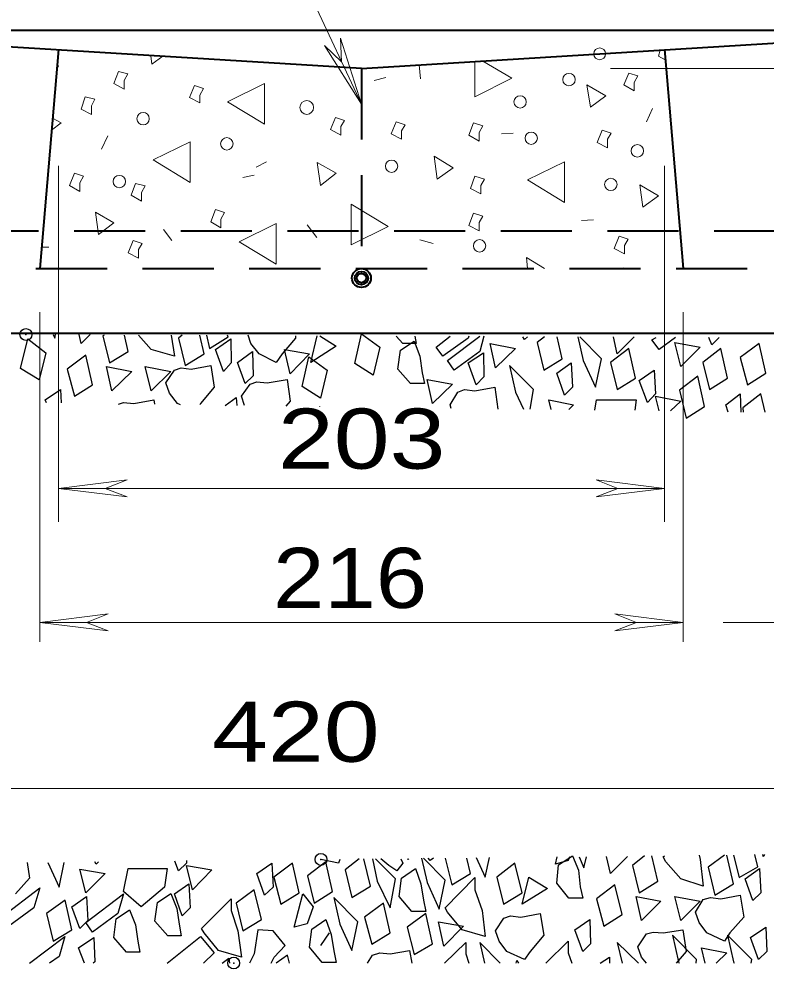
# Model space of a CAD drawing. Extents: x 312583 to 312854, y 144419 to 144597.
# Drawn here: x 312650.91 to 312660.36, y 144443.05 to 144455.06 of the extents above; entities that cross this region are included whole.
import ezdxf

# ---------------------------------------------------------------- set-up
doc = ezdxf.new("R2010")
doc.units = 0
doc.header["$LTSCALE"] = 0.3
doc.header["$PDMODE"] = 32
doc.header["$PDSIZE"] = 0.15
doc.linetypes.add('MEDIUM_DASHED', pattern=[4.5, 3, -1.5])
doc.layers.add('1', color=7, linetype='Continuous', lineweight=25)
doc.layers.add('2', color=7, linetype='Continuous', lineweight=13)

msp = doc.modelspace()

# ---------------------------------------------------------------- linework, layer by layer
at = {"layer": '1', "lineweight": 40}
for p, q in [((312655.2448, 144454.4368), (312647.3405, 144454.9198)), ((312647.5781, 144454.9198), (312662.9115, 144454.9198)), ((312655.2448, 144454.4368), (312663.1491, 144454.9198)), ((312651.4115, 144454.6744), (312651.1738, 144451.9068)), ((312659.0781, 144454.6744), (312659.3158, 144451.9068)), ((312626.2571, 144451.0864), (312669.6198, 144451.0864))]:
    msp.add_line(p, q, dxfattribs=at)
at = {"layer": '1', "linetype": 'MEDIUM_DASHED', "lineweight": 40}
for p, q in [((312655.2448, 144454.4368), (312655.2448, 144451.9068)), ((312643.5071, 144452.3821), (312667.7031, 144452.3821)), ((312628.1738, 144451.9068), (312667.4655, 144451.9068))]:
    msp.add_line(p, q, dxfattribs=at)
at = {"layer": '1'}
for p, q in [((312652.2931, 144450.8564), (312652.2471, 144451.0634)), ((312653.2515, 144450.8258), (312653.1978, 144451.0634)), ((312653.5581, 144451.0404), (312653.5505, 144451.0634)), ((312654.7158, 144451.0558), (312654.9228, 144450.9254)), ((312656.6018, 144451.0481), (312656.5941, 144451.0251)), ((312656.7935, 144451.0481), (312656.7398, 144450.8564)), ((312657.7825, 144450.7644), (312657.7211, 144451.0404)), ((312658.2808, 144450.7644), (312658.0048, 144451.0404)), ((312651.4345, 144450.3734), (312651.4421, 144450.2048)), ((312657.3761, 144450.1281), (312657.4221, 144450.3734)), ((312653.5198, 144450.1741), (312653.6578, 144450.2738)), ((312653.6578, 144450.2738), (312653.6655, 144450.1741)), ((312659.2851, 144450.2278), (312659.1548, 144450.1051)), ((312660.0365, 144450.3198), (312660.0441, 144450.0898)), ((312653.2055, 144450.1971), (312653.1978, 144450.1818)), ((312654.7158, 144450.1588), (312654.7158, 144450.1664)), ((312657.9281, 144450.1818), (312657.8668, 144450.1204)), ((312658.9938, 144444.1558), (312658.9171, 144444.4778)), ((312659.9521, 144444.1251), (312659.8678, 144444.4854)), ((312660.2588, 144444.3398), (312660.2205, 144444.4931)), ((312655.3598, 144444.0944), (312655.2755, 144444.4394)), ((312655.6741, 144444.1864), (312655.4211, 144444.4394)), ((312656.3028, 144444.1711), (312656.0268, 144444.4471)), ((312656.6248, 144444.2554), (312656.5788, 144444.4471)), ((312654.7311, 144443.3431), (312654.8385, 144443.5041)), ((312651.4191, 144443.2051), (312651.2965, 144443.1208)), ((312653.4815, 144443.1208), (312653.5658, 144443.1821)), ((312653.5658, 144443.1821), (312653.5735, 144443.1208)), ((312656.5635, 144443.2358), (312656.6018, 144443.1208)), ((312657.8591, 144443.2511), (312657.9051, 144443.1208)), ((312658.2655, 144443.1208), (312658.3805, 144443.1974)), ((312658.3805, 144443.1974), (312658.3805, 144443.1208)), ((312659.4768, 144443.1208), (312659.4845, 144443.1668)), ((312659.8678, 144443.2511), (312659.7298, 144443.1208)), ((312660.1745, 144443.1208), (312660.1821, 144443.1668))]:
    msp.add_line(p, q, dxfattribs=at)
for points in [[(312651.3425, 144451.0711), (312651.3655, 144451.0251), (312651.3731, 144451.0711)], [(312651.8101, 144451.0711), (312651.6951, 144450.9561), (312651.6721, 144451.0711)], [(312651.9865, 144451.0634), (312651.9711, 144451.0558), (312652.0555, 144450.7108), (312652.2931, 144450.8564)], [(312652.8375, 144451.0634), (312652.8758, 144450.7951), (312652.5845, 144450.8794), (312652.4235, 144451.0634)], [(312652.9755, 144451.0634), (312652.9295, 144451.0251), (312653.0138, 144450.6801), (312653.2515, 144450.8258)], [(312653.2821, 144451.0634), (312653.3205, 144450.8948), (312653.5581, 144451.0404)], [(312654.2405, 144450.8258), (312654.1638, 144450.7184), (312653.9491, 144450.8258), (312653.8418, 144450.9561), (312653.8111, 144451.0634)], [(312654.4091, 144451.0558), (312654.4091, 144451.0251), (312654.2405, 144450.8258)], [(312654.9228, 144450.9254), (312654.6008, 144450.7184), (312654.6851, 144451.0558)], [(312655.9195, 144451.0481), (312655.9348, 144450.9561), (312655.7661, 144450.9561), (312655.6818, 144451.0481)], [(312656.5941, 144451.0251), (312656.2721, 144450.7951), (312656.1878, 144450.9101), (312656.3641, 144451.0481)], [(312656.7398, 144450.8564), (312656.4178, 144450.6188), (312656.3335, 144450.7414), (312656.7398, 144451.0481)], [(312657.3455, 144451.0404), (312657.3071, 144451.0098), (312657.2841, 144451.0404)], [(312657.5601, 144451.0404), (312657.4681, 144450.9714), (312657.5525, 144450.6188), (312657.7825, 144450.7644)], [(312657.9818, 144451.0404), (312658.0508, 144450.7414), (312658.2041, 144450.4041), (312658.2808, 144450.7644)], [(312658.6948, 144451.0404), (312658.4801, 144450.8258), (312658.4341, 144451.0404)], [(312659.2161, 144451.0328), (312659.0091, 144450.8794), (312658.9171, 144451.0021), (312658.9708, 144451.0328)], [(312659.7681, 144451.0328), (312659.6761, 144450.9408), (312659.6378, 144451.0328)], [(312652.9525, 144450.1818), (312652.9141, 144450.1971), (312652.8145, 144450.3274), (312652.7685, 144450.4578), (312652.8758, 144450.6188), (312652.9601, 144450.6494), (312653.0905, 144450.6341), (312653.3358, 144450.6801), (312653.3818, 144450.4041), (312653.2055, 144450.1971)], [(312657.4221, 144450.3734), (312657.1155, 144450.6801), (312657.1921, 144450.3428), (312657.2918, 144450.1281)], [(312653.7651, 144450.1741), (312653.7268, 144450.2891), (312653.8341, 144450.4424), (312653.9185, 144450.4731), (312654.0488, 144450.4578), (312654.3018, 144450.5038), (312654.3401, 144450.2278), (312654.2865, 144450.1664)], [(312651.2581, 144450.2048), (312651.2428, 144450.2431), (312651.4345, 144450.3734)], [(312656.3795, 144450.1358), (312656.3641, 144450.1818), (312656.4638, 144450.3428), (312656.5481, 144450.3734), (312656.6785, 144450.3581), (312656.9315, 144450.4041), (312656.9698, 144450.1281)], [(312652.1705, 144450.1894), (312652.2318, 144450.2124), (312652.3621, 144450.1971), (312652.6151, 144450.2431), (312652.6228, 144450.1894)], [(312657.6445, 144450.1204), (312657.6138, 144450.2431), (312657.9281, 144450.1818)], [(312658.1965, 144450.1128), (312658.2195, 144450.2431), (312658.7178, 144450.2431), (312658.7025, 144450.1128)], [(312659.0091, 144450.1051), (312658.9631, 144450.2891), (312659.2851, 144450.2278)], [(312659.8831, 144450.0898), (312659.8525, 144450.1818), (312660.0365, 144450.3198)], [(312660.3508, 144450.0898), (312660.2971, 144450.3198), (312660.0671, 144450.1434), (312660.0748, 144450.0898)], [(312657.8745, 144444.4624), (312657.8591, 144444.4164), (312657.6981, 144444.3704), (312657.7211, 144444.4624)], [(312657.9971, 144444.4624), (312658.0585, 144444.3244), (312658.0891, 144444.4624)], [(312658.6105, 144444.4701), (312658.3958, 144444.2554), (312658.3421, 144444.4701)], [(312658.8251, 144444.4778), (312658.6718, 144444.3551), (312658.7561, 144444.0101), (312658.9938, 144444.1558)], [(312659.5151, 144444.4854), (312659.5305, 144444.4318), (312659.5688, 144444.0944), (312659.2851, 144444.1864), (312659.0935, 144444.4011), (312659.0628, 144444.4624), (312659.0781, 144444.4778)], [(312659.8371, 144444.4854), (312659.6301, 144444.3321), (312659.7145, 144443.9794), (312659.9521, 144444.1251)], [(312659.9521, 144444.4854), (312660.0211, 144444.2018), (312660.2588, 144444.3398)], [(312660.3431, 144444.4931), (312660.3278, 144444.4701), (312660.3201, 144444.4931)], [(312651.0128, 144444.3934), (312651.0435, 144444.1941), (312650.8671, 144443.9948)], [(312651.2735, 144444.3934), (312651.4191, 144444.0791), (312651.4805, 144444.3934)], [(312651.9175, 144444.4011), (312651.8868, 144444.3704), (312651.8715, 144444.4011)], [(312653.0291, 144444.4164), (312653.0291, 144444.3858), (312652.9295, 144444.2861), (312652.8835, 144444.4088)], [(312654.9688, 144444.4318), (312654.9535, 144444.3858), (312654.7311, 144444.4318)], [(312655.2141, 144444.4394), (312655.0378, 144444.3014), (312655.1221, 144443.9488), (312655.3598, 144444.0944)], [(312655.3828, 144444.4394), (312655.4441, 144444.1558), (312655.6051, 144443.8184), (312655.6741, 144444.1864)], [(312655.7431, 144444.4394), (312655.7661, 144444.3858), (312655.6895, 144444.2861), (312655.5898, 144444.3551), (312655.4901, 144444.4394)], [(312655.8275, 144444.4394), (312655.8351, 144444.4318), (312655.8428, 144444.4394)], [(312656.0038, 144444.4471), (312656.0728, 144444.1404), (312656.2261, 144443.8031), (312656.3028, 144444.1711)], [(312656.1571, 144444.4471), (312656.1111, 144444.4164), (312656.0881, 144444.4471)], [(312656.3028, 144444.4471), (312656.3871, 144444.1098), (312656.6248, 144444.2554)], [(312656.6938, 144444.4548), (312656.8088, 144444.2094), (312656.8625, 144444.4548)], [(312654.1025, 144443.1208), (312654.1408, 144443.1974), (312654.2788, 144443.3431), (312654.1255, 144443.5271), (312653.9338, 144443.5424), (312653.8878, 144443.2358), (312653.8265, 144443.1208)], [(312658.8481, 144443.1208), (312658.7868, 144443.1974), (312658.7408, 144443.3278), (312658.8481, 144443.4888), (312658.9325, 144443.5118), (312659.0628, 144443.5041), (312659.3081, 144443.5424), (312659.3541, 144443.2664), (312659.2238, 144443.1208)], [(312651.0435, 144443.1208), (312651.4881, 144443.4581), (312651.4191, 144443.2051)], [(312651.7411, 144443.1208), (312651.6645, 144443.3124), (312651.8561, 144443.4428)], [(312651.8561, 144443.4428), (312651.8715, 144443.1361), (312651.8485, 144443.1208)], [(312652.7915, 144443.1208), (312652.7838, 144443.1208), (312653.2055, 144443.4581)], [(312653.2055, 144443.4581), (312653.3818, 144443.2511), (312653.2438, 144443.1208)], [(312656.2951, 144443.1208), (312656.5635, 144443.3814), (312656.5635, 144443.2358)], [(312657.0005, 144443.1208), (312656.7398, 144443.3814), (312656.8011, 144443.1208)], [(312657.5755, 144443.1208), (312657.8591, 144443.3968), (312657.8591, 144443.2511)], [(312658.7485, 144443.1208), (312658.4801, 144443.3814), (312658.5415, 144443.1208)], [(312659.4845, 144443.1668), (312659.1778, 144443.4734), (312659.2545, 144443.1361), (312659.2621, 144443.1208)], [(312660.1821, 144443.1668), (312659.8755, 144443.4734), (312659.9521, 144443.1361), (312659.9598, 144443.1208)], [(312655.3215, 144443.1208), (312655.3828, 144443.2204), (312655.4748, 144443.2511), (312655.6051, 144443.2358), (312655.8505, 144443.2818), (312655.8811, 144443.1208)], [(312659.5918, 144443.1208), (312659.5458, 144443.3124), (312659.8678, 144443.2511)], [(312654.3325, 144443.1208), (312654.3095, 144443.2204), (312654.1638, 144443.1208)], [(312657.1998, 144443.1208), (312657.2075, 144443.1514), (312657.2305, 144443.1208)]]:
    msp.add_lwpolyline(points, dxfattribs=at)
for points in [[(312655.1605, 144450.7031), (312655.2448, 144451.0788), (312655.4748, 144450.9101), (312655.3905, 144450.5574)], [(312650.9285, 144450.6418), (312651.0205, 144451.0174), (312651.2505, 144450.8411), (312651.1661, 144450.4961)], [(312653.5888, 144451.0174), (312653.5965, 144450.7108), (312653.4968, 144450.6034), (312653.3971, 144450.8794)], [(312655.9118, 144450.9868), (312655.9808, 144450.7951), (312656.0115, 144450.5881), (312656.0421, 144450.4501), (312655.8658, 144450.4501), (312655.7048, 144450.6341), (312655.7355, 144450.8718)], [(312657.1921, 144450.8948), (312656.9391, 144450.6494), (312656.8701, 144450.9561)], [(312659.5305, 144450.9101), (312659.2851, 144450.6648), (312659.2085, 144450.9714)], [(312660.3585, 144450.5804), (312660.2741, 144450.9561), (312660.0365, 144450.7798), (312660.1285, 144450.4348)], [(312653.8648, 144450.8564), (312653.8725, 144450.5498), (312653.7728, 144450.4501), (312653.6731, 144450.7184)], [(312654.5855, 144450.8258), (312654.3401, 144450.5728), (312654.2711, 144450.8794)], [(312656.7858, 144450.8411), (312656.7935, 144450.5344), (312656.6938, 144450.4348), (312656.5941, 144450.7108)], [(312658.7101, 144450.5191), (312658.6258, 144450.8948), (312658.3958, 144450.7184), (312658.4801, 144450.3734)], [(312659.8755, 144450.5191), (312659.7911, 144450.8948), (312659.5611, 144450.7184), (312659.6455, 144450.3734)], [(312651.8408, 144450.4348), (312651.7565, 144450.8104), (312651.5188, 144450.6341), (312651.6108, 144450.2891)], [(312654.4935, 144450.4118), (312654.5778, 144450.7874), (312654.8078, 144450.6188), (312654.7235, 144450.2661)], [(312657.8975, 144450.7108), (312657.9128, 144450.4041), (312657.8131, 144450.3044), (312657.7135, 144450.5804)], [(312652.3391, 144450.6034), (312652.0861, 144450.3581), (312652.0171, 144450.6648)], [(312652.8298, 144450.6034), (312652.5845, 144450.3581), (312652.5078, 144450.6648)], [(312658.9478, 144450.6188), (312658.9631, 144450.3198), (312658.8635, 144450.2124), (312658.7561, 144450.4884)], [(312656.3948, 144450.4424), (312656.1418, 144450.1971), (312656.0728, 144450.5038)], [(312659.5841, 144450.1588), (312659.4998, 144450.5421), (312659.2698, 144450.3658), (312659.3541, 144450.0131)], [(312657.9128, 144444.4778), (312657.9895, 144444.2938), (312658.0125, 144444.0868), (312658.0431, 144443.9411), (312657.8668, 144443.9411), (312657.7135, 144444.1328), (312657.7365, 144444.3628)], [(312653.3511, 144444.3014), (312653.1058, 144444.0484), (312653.0291, 144444.3551)], [(312654.1101, 144444.3858), (312654.1255, 144444.0791), (312654.0181, 144443.9794), (312653.9185, 144444.2554)], [(312654.4551, 144444.0101), (312654.3708, 144444.3858), (312654.1331, 144444.2094), (312654.2251, 144443.8644)], [(312654.8768, 144444.0254), (312654.7925, 144444.4011), (312654.5625, 144444.2248), (312654.6468, 144443.8798)], [(312657.2765, 144444.0101), (312657.1845, 144444.3858), (312656.9545, 144444.2094), (312657.0388, 144443.8644)], [(312652.0018, 144444.2554), (312651.7565, 144444.0101), (312651.6798, 144444.3091)], [(312652.7531, 144444.0791), (312652.4541, 144443.8338), (312652.2318, 144444.0254), (312652.2931, 144444.3168), (312652.7838, 144444.3168)], [(312655.9271, 144444.3168), (312655.9961, 144444.1251), (312656.0268, 144443.9181), (312656.0575, 144443.7724), (312655.8811, 144443.7724), (312655.7201, 144443.9641), (312655.7508, 144444.1941)], [(312660.2818, 144444.3168), (312660.2971, 144444.0101), (312660.1975, 144443.9104), (312660.0978, 144444.1864)], [(312653.0598, 144444.1251), (312653.0751, 144443.8184), (312652.9755, 144443.7188), (312652.8758, 144443.9948)], [(312656.6785, 144444.0484), (312656.7705, 144443.7878), (312656.8088, 144443.4581), (312656.5175, 144443.5424), (312656.3335, 144443.7648), (312656.3028, 144443.8184), (312656.6785, 144444.2018)], [(312657.5985, 144444.0638), (312657.2765, 144443.8644), (312657.3608, 144444.2094)], [(312658.5415, 144443.7341), (312658.4495, 144444.1098), (312658.2195, 144443.9334), (312658.3115, 144443.5884)], [(312651.0971, 144443.8184), (312650.7828, 144443.5884), (312650.6908, 144443.7034), (312651.1738, 144444.0714)], [(312652.1628, 144443.7494), (312651.8408, 144443.5118), (312651.7565, 144443.6344), (312652.2318, 144443.9948)], [(312652.8298, 144444.0024), (312652.9065, 144443.8108), (312652.9371, 144443.6114), (312652.9601, 144443.4658), (312652.7915, 144443.4658), (312652.6305, 144443.6498), (312652.6611, 144443.8874)], [(312653.9798, 144443.6728), (312653.8878, 144444.0484), (312653.6578, 144443.8798), (312653.7421, 144443.5271)], [(312654.6315, 144443.8338), (312654.5548, 144443.6191), (312654.3938, 144443.5731), (312654.5011, 144443.9948)], [(312659.9061, 144443.5041), (312659.8371, 144443.3968), (312659.6148, 144443.5041), (312659.5151, 144443.6344), (312659.4691, 144443.7648), (312659.5688, 144443.9258), (312659.6608, 144443.9488), (312659.7911, 144443.9334), (312660.0365, 144443.9794), (312660.0825, 144443.7034)], [(312651.5801, 144443.5424), (312651.4958, 144443.9181), (312651.2581, 144443.7494), (312651.3425, 144443.3968)], [(312651.7641, 144443.9641), (312651.7795, 144443.6574), (312651.6798, 144443.5578), (312651.5801, 144443.8338)], [(312653.5965, 144443.7878), (312653.6808, 144443.5271), (312653.7268, 144443.1974), (312653.4355, 144443.2818), (312653.2515, 144443.5041), (312653.2208, 144443.5578), (312653.5965, 144443.9334)], [(312655.1988, 144443.6421), (312654.8921, 144443.9488), (312654.9688, 144443.6114), (312655.1221, 144443.2818)], [(312655.6051, 144443.5041), (312655.5208, 144443.8798), (312655.2831, 144443.7034), (312655.3751, 144443.3584)], [(312659.0321, 144443.9028), (312658.7868, 144443.6574), (312658.7178, 144443.9641)], [(312659.5305, 144443.9028), (312659.2851, 144443.6574), (312659.2085, 144443.9641)], [(312652.3085, 144443.7954), (312652.3851, 144443.6038), (312652.4158, 144443.3968), (312652.4388, 144443.2588), (312652.2701, 144443.2588), (312652.1091, 144443.4428), (312652.1398, 144443.6804)], [(312656.1418, 144443.3661), (312656.0575, 144443.7494), (312655.8198, 144443.5731), (312655.9118, 144443.2281)], [(312657.3761, 144443.2664), (312657.3071, 144443.1668), (312657.0848, 144443.2664), (312656.9851, 144443.3968), (312656.9391, 144443.5271), (312657.0465, 144443.6881), (312657.1308, 144443.7188), (312657.2611, 144443.7034), (312657.5065, 144443.7494), (312657.5525, 144443.4734)], [(312654.7925, 144443.6728), (312654.8615, 144443.4811), (312654.8921, 144443.2741), (312654.9228, 144443.1284), (312654.7465, 144443.1284), (312654.5855, 144443.3201), (312654.6161, 144443.5501)], [(312656.5328, 144443.5884), (312656.2875, 144443.3354), (312656.2185, 144443.6421)], [(312658.1351, 144443.6728), (312658.1428, 144443.3661), (312658.0431, 144443.2664), (312657.9435, 144443.5424)], [(312660.3585, 144443.5731), (312660.3738, 144443.2664), (312660.2665, 144443.1668), (312660.1668, 144443.4428)]]:
    msp.add_lwpolyline(points, close=True, dxfattribs=at)
at = {"layer": '1', "lineweight": 40}
for radius in [0.1198, 0.0838, 0.0587]:
    msp.add_circle((312655.2429, 144451.7851), radius, dxfattribs=at)
at = {"layer": '1'}
for p in [(312650.9975, 144451.0711), (312654.7311, 144444.4318), (312653.6271, 144443.1208)]:
    msp.add_point(p, dxfattribs=at)
at = {"layer": '2'}
for p, q in [((312652.8375, 144459.1211), (312655.2448, 144453.9844)), ((312654.9765, 144454.8201), (312654.9918, 144454.5211)), ((312655.2448, 144453.9844), (312654.9765, 144454.8201)), ((312654.7771, 144454.7281), (312654.9918, 144454.5211)), ((312655.2448, 144453.9844), (312654.7771, 144454.7281)), ((312652.5768, 144454.5978), (312652.5921, 144454.4904)), ((312652.5921, 144454.4904), (312652.7301, 144454.5901)), ((312655.9731, 144454.4828), (312655.9885, 144454.3064)), ((312658.3958, 144454.4368), (312672.7401, 144454.4368)), ((312655.4058, 144454.2834), (312655.5515, 144454.3218)), ((312658.9248, 144453.9308), (312658.8481, 144453.7621)), ((312657.0158, 144453.6088), (312657.1615, 144453.6164)), ((312652.0325, 144453.5858), (312651.9558, 144453.4171)), ((312653.9108, 144453.1871), (312654.0411, 144453.2561)), ((312651.4115, 144453.2024), (312651.4115, 144448.7021)), ((312659.0781, 144453.2024), (312659.0781, 144448.7021)), ((312653.7421, 144453.0568), (312653.8878, 144453.0874)), ((312658.0278, 144452.5124), (312658.1811, 144452.5201)), ((312652.7378, 144452.3974), (312652.8451, 144452.2594)), ((312654.5548, 144452.4588), (312654.6775, 144452.2978)), ((312655.9808, 144452.2671), (312656.1495, 144452.2211)), ((312651.1968, 144452.1751), (312651.2888, 144452.1751)), ((312651.1738, 144451.3548), (312651.1738, 144447.1841)), ((312659.3158, 144451.3548), (312659.3158, 144447.1841)), ((312651.4115, 144449.1238), (312652.2778, 144449.2311)), ((312652.2778, 144449.2311), (312652.0018, 144449.1238)), ((312658.2118, 144449.2311), (312658.4878, 144449.1238)), ((312659.0781, 144449.1238), (312658.2118, 144449.2311)), ((312651.4115, 144449.1238), (312659.0781, 144449.1238)), ((312651.4115, 144449.1238), (312652.2778, 144449.0164)), ((312652.2778, 144449.0164), (312652.0018, 144449.1238)), ((312658.2118, 144449.0164), (312658.4878, 144449.1238)), ((312659.0781, 144449.1238), (312658.2118, 144449.0164)), ((312651.1738, 144447.4294), (312652.0401, 144447.5368)), ((312652.0401, 144447.5368), (312651.7641, 144447.4294)), ((312658.4495, 144447.5368), (312658.7255, 144447.4294)), ((312659.3158, 144447.4294), (312658.4495, 144447.5368)), ((312651.1738, 144447.4294), (312659.3158, 144447.4294)), ((312651.1738, 144447.4294), (312652.0401, 144447.3221)), ((312652.0401, 144447.3221), (312651.7641, 144447.4294)), ((312658.4495, 144447.3221), (312658.7255, 144447.4294)), ((312659.3158, 144447.4294), (312658.4495, 144447.3221)), ((312659.8218, 144447.4294), (312661.2325, 144447.4294)), ((312647.3405, 144445.3288), (312663.1491, 144445.3288))]:
    msp.add_line(p, q, dxfattribs=at)
for points in [[(312659.0245, 144454.6668), (312659.0015, 144454.5901), (312659.0858, 144454.5441)], [(312651.3885, 144454.4214), (312651.4115, 144454.4674), (312651.3961, 144454.4674)], [(312656.6785, 144454.5288), (312656.6785, 144454.0764), (312657.1461, 144454.3141), (312656.7781, 144454.5288)], [(312651.3195, 144453.6548), (312651.4421, 144453.7468), (312651.3348, 144453.8081)], [(312657.5601, 144451.9068), (312657.3301, 144452.0448), (312657.3455, 144451.9068)], [(312658.5951, 144451.9068), (312658.5645, 144451.9144), (312658.5645, 144451.9068)]]:
    msp.add_lwpolyline(points, dxfattribs=at)
for points in [[(312652.2395, 144454.2834), (312652.2855, 144454.3678), (312652.1705, 144454.3984), (312652.1091, 144454.2451), (312652.2395, 144454.1761)], [(312658.6948, 144454.2604), (312658.7408, 144454.3448), (312658.6258, 144454.3754), (312658.5645, 144454.2298), (312658.6948, 144454.1531)], [(312653.1978, 144454.0994), (312653.2438, 144454.1838), (312653.1288, 144454.2221), (312653.0675, 144454.0688), (312653.1978, 144453.9998)], [(312654.0181, 144453.7314), (312654.0181, 144454.2451), (312653.5505, 144454.0151)], [(312658.1428, 144453.9461), (312658.3345, 144454.0918), (312658.0968, 144454.2298)], [(312651.8255, 144453.9614), (312651.8715, 144454.0458), (312651.7488, 144454.0764), (312651.6951, 144453.9231), (312651.8255, 144453.8541)], [(312654.9841, 144453.7008), (312655.0301, 144453.7774), (312654.9151, 144453.8158), (312654.8538, 144453.6624), (312654.9841, 144453.5934)], [(312655.7508, 144453.6471), (312655.7968, 144453.7238), (312655.6818, 144453.7621), (312655.6205, 144453.6088), (312655.7508, 144453.5398)], [(312656.7321, 144453.6241), (312656.7781, 144453.7084), (312656.6631, 144453.7468), (312656.6018, 144453.5934), (312656.7321, 144453.5168)], [(312658.3575, 144453.5398), (312658.4035, 144453.6164), (312658.2885, 144453.6548), (312658.2271, 144453.5014), (312658.3575, 144453.4324)], [(312653.0751, 144452.9954), (312653.0751, 144453.5091), (312652.6075, 144453.2791)], [(312654.7235, 144452.9571), (312654.9228, 144453.1104), (312654.6851, 144453.2484)], [(312656.2031, 144453.0338), (312656.4025, 144453.1794), (312656.1648, 144453.3251)], [(312657.8131, 144452.7424), (312657.8131, 144453.2561), (312657.3455, 144453.0261)], [(312651.6798, 144452.9878), (312651.7258, 144453.0721), (312651.6108, 144453.1104), (312651.5495, 144452.9571), (312651.6798, 144452.8804)], [(312656.7551, 144452.9571), (312656.8011, 144453.0338), (312656.6785, 144453.0721), (312656.6248, 144452.9188), (312656.7551, 144452.8498)], [(312652.4618, 144452.8651), (312652.5078, 144452.9494), (312652.3851, 144452.9801), (312652.3315, 144452.8344), (312652.4618, 144452.7578)], [(312658.8021, 144452.6811), (312659.0015, 144452.8268), (312658.7638, 144452.9648)], [(312653.4661, 144452.5278), (312653.5121, 144452.6121), (312653.3971, 144452.6504), (312653.3358, 144452.4971), (312653.4661, 144452.4204)], [(312655.1145, 144452.7194), (312655.1145, 144452.2058), (312655.5821, 144452.4358)], [(312651.9175, 144452.3361), (312652.1091, 144452.4818), (312651.8791, 144452.6198)], [(312656.7321, 144452.4894), (312656.7781, 144452.5661), (312656.6631, 144452.6044), (312656.6018, 144452.4511), (312656.7321, 144452.3821)], [(312654.1638, 144451.9604), (312654.1638, 144452.4741), (312653.6961, 144452.2441)], [(312658.5721, 144452.1981), (312658.6181, 144452.2748), (312658.5031, 144452.3131), (312658.4418, 144452.1598), (312658.5721, 144452.0908)], [(312652.4235, 144452.1444), (312652.4695, 144452.2211), (312652.3545, 144452.2594), (312652.2931, 144452.1061), (312652.4235, 144452.0371)]]:
    msp.add_lwpolyline(points, close=True, dxfattribs=at)
for centre, radius in [((312657.8691, 144454.2952), 0.0784), ((312657.251, 144454.0125), 0.0784), ((312654.5508, 144453.9423), 0.0865), ((312652.4804, 144453.8007), 0.0784), ((312657.3918, 144453.5534), 0.0784), ((312653.5403, 144453.4825), 0.0784), ((312658.7345, 144453.3944), 0.0784), ((312655.6247, 144453.1998), 0.0784), ((312652.1795, 144453.0053), 0.0784), ((312658.3991, 144452.9698), 0.0784), ((312656.7383, 144452.1926), 0.0784)]:
    msp.add_circle(centre, radius, dxfattribs=at)
msp.add_point((312658.2578, 144454.6208), dxfattribs=at)

# ---------------------------------------------------------------- texts
for s, width, p in [('203 ', 1.25, (312654.1861, 144449.3739)), ('216 ', 1.15, (312654.1249, 144447.6125)), ('420 ', 1.25, (312653.3539, 144445.6671))]:
    msp.add_text(s, height=0.76, dxfattribs=dict(at, width=width)).set_placement(p)

doc.saveas('drawing.dxf')
